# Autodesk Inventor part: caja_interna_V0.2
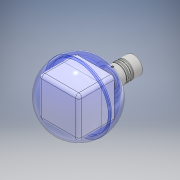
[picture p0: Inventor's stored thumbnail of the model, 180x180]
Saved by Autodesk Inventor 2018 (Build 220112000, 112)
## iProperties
Created: 2018-09
Part Number: caja_interna_V0.2
Material: Generic
Document SubType Name: Modeling
Designer: Gordillo
Density: 1 g/cm^3
Appearance: Default
Author: Gordillo
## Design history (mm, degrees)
sketch "Sketch1"
  geometry: L1 (125, 125)-(-125, 125); L2 (-125, 125)-(-125, -125); L3 (-125, -125)-(125, -125); L4 (125, -125)-(125, 125); L5 (-175, 0)-(175, 0) reference; L6 (0, -175)-(0, 175) reference; 1 further point
  constraints: 8 end point, 2 parallel, 1 horizontal, 1 perpendicular, 2 other
  dimensions: "d0" = 250 distance of L3.end L2.end; "d1" = 250 distance of L2.end L1.end
extrude "Extrusion1" new body sketch "Sketch1" distance "d2" = 220; taper "d3" = 0 deg
fillet "Fillet1" dims "d5" = 20
sketch "Sketch2"
  geometry: L1 (20, 125)-(220, 125) reference; L2 (120, 125)-(120, -125); L3 (220, -125)-(20, -125) reference; L4 (120, 125)-(120, 205); L5 (120, 0)-(-80, 0); L6 (-153.152, 0)-(282.192, 0) reference; A1 r 203.001 centre (122.991, 2.021) between (120, 205) and (-80, 0); 1 further point
  constraints: 6 end point, 3 midpoint, 2 point on circle, 1 centre point, 1 horizontal, 1 vertical
  dimensions: "d6" = 200 distance of L5.start L5.end; "d8" = 80 distance of L2.start L4.end
revolve "Revolution1" sketch "Sketch2" stored, may be unused: angle "d9" = 90 deg
combine "Combine1"
shell "Shell2" dims "d10" = 25
sketch "Sketch3"
  geometry: L1 (100, 100)-(100, -100) reference; L2 (100, -100)-(-100, -100) reference; L3 (-100, -100)-(-100, 100) reference; L4 (-100, 100)-(100, 100) reference; L5 (105, 125)-(-105, 125) reference; L6 (-125, 105)-(-125, -105) reference; L7 (-105, -125)-(105, -125) reference; L8 (125, -105)-(125, 105) reference; L9 (-105, 125)-(105, 125) reference; L10 (125, 105)-(125, -105) reference; L11 (105, -125)-(-105, -125) reference; L12 (-125, -105)-(-125, 105) reference; L13 (-105, 125)-(105, 125) reference; L14 (105, 125)-(-105, 125); L15 (-105, 125)-(-125, 105); L16 (-125, -105)-(-125, 105) reference; L17 (-125, -105)-(-105, -125); L18 (125, 105)-(125, -105) reference; L19 (105, -125)-(125, -105); L20 (125, -105)-(125, 105); L21 (-125, 105)-(-105, 105) reference; L22 (-125, 105)-(-125, -105); L23 (-105, -125)-(105, -125); C1 r 205 at (0, 0) reference; C2 r 189 at (0, 0); C3 r 205 at (0, 0) reference; A1 r 20 centre (105, 105) between (125, 105) and (105, 125) reference; A2 r 20 centre (-105, 105) between (-105, 125) and (-125, 105) reference; A3 r 20 centre (-105, -105) between (-125, -105) and (-105, -125) reference; A4 r 20 centre (105, -105) between (105, -125) and (125, -105) reference; A5 r 20 centre (-105, 105) between (-105, 125) and (-125, 105) reference; A6 r 20 centre (105, 105) between (125, 105) and (105, 125) reference; A7 r 20 centre (105, -105) between (105, -125) and (125, -105) reference; A8 r 20 centre (-105, -105) between (-125, -105) and (-105, -125) reference; A9 r 20 centre (105, 105) between (125, 105) and (105, 125) reference; A10 r 20 centre (105, 105) between (125, 105) and (105, 125); A11 r 20 centre (105, -105) between (105, -125) and (125, -105) reference; A12 r 20 centre (105, -105) between (105, -125) and (125, -105); A13 r 20 centre (-105, -105) between (-125, -105) and (-105, -125); A14 r 20 centre (-105, 105) between (-105, 125) and (-125, 105) reference; A15 r 20 centre (-105, 105) between (-105, 125) and (-125, 105); A16 r 20 centre (-105, -105) between (-125, -105) and (-105, -125); A17 r 20 centre (-105, -105) between (-125, -105) and (-105, -125); A18 r 20 centre (105, -105) between (105, -125) and (125, -105); A19 r 20 centre (-105, -105) between (-125, -105) and (-105, -125) reference; A20 r 20 centre (-105, -105) between (-125, -105) and (-105, -125); 1 further point
  constraints: 16 point on circle, 14 end point, 9 centre point, 3 perpendicular, 3 tangent, 2 collinear, 1 concentric, 1 vertical
  dimensions: "d11" = 16 radial gap between concentric circles of C1 C2
extrude "Extrusion2" join sketch "Sketch3" distance "d12" = 20; taper "d13" = 0 deg
sketch "Sketch4"
  geometry: L1 (189, 140)-(-189, 140) reference; L2 (205, 120)-(-205, 120) reference; L3 (189, 120)-(189, 140) reference; L4 (189, 140)-(-189, 140) reference; L5 (-189, 120)-(189, 120) reference; L6 (-125, 20)-(-125, 220) reference; L7 (-125, 220)-(-105, 220) reference; L8 (-205, 120)-(-189, 120); L9 (-189, 120)-(-189, 140); L10 (205, 120)-(-205, 120) reference; L11 (-189, 140)-(-125, 140); L12 (0, 120)-(0, 320); L13 (-125, 140)-(0, 140); L14 (0, -168.98)-(0, 453.807) reference; L15 (0, 304)-(-55, 304); L16 (-55, 304)-(-55, 315.014); L17 (0, 304)-(0, 298); L18 (0, 304)-(-55, 304); L19 (-55, 304)-(-55, 315.014); L20 (-87, 304.444)-(-67, 304.444); L21 (-67, 304.444)-(-67, 311.765); A1 r 195 centre (-10.071, 125.26) between (0, 320) and (-205, 120); A2 r 177.861 centre (-12.205, 120.558) between (0, 298) and (-189, 140); A3 r 195 centre (-10.071, 125.26) between (-55, 315.014) and (-205, 120); A4 r 177.861 centre (-12.205, 120.558) between (0, 298) and (-189, 140); 2 further points
  constraints: 24 end point, 11 point on circle, 5 point on line, 4 centre point, 4 perpendicular, 3 vertical, 2 collinear, 2 concentric, 2 midpoint, 1 horizontal
  dimensions: "d14" = 200 distance of L12.start L12.end; "d15" = 195 radius of A1; "d16" = 22 distance of L12.end L17.end; "d26" = 55 distance of L15.start L15.end; "d27" = 16 distance from line of L12.end L15; "d28" = 177.86112 radius of A2; "d30" = 12 distance between parallel lines of L16 L21; "d31" = 20 distance of L20.start L20.end
  node "Projected Loop3"
  node "Projected Loop4"
derived "tubo_electrovalvula_V0.1.ipt"
feature "Move Body1"
feature "Move Body3"
revolve "Revolution4" stored, may be unused: angle "d32" = 90 deg
node "cajacorchopan"
node "semicirculo_inferior"
node "Projected Loop1"
node "Projected Loop2"
feature "Solid1::tubo_electrovalvula_V0.1.ipt" dims "d18" = 10
tag "TaggingFeature1"
node "semicirculo_superior"
node "tubo inflado"
other parameters: "d19" = 270 deg, "d23" = 0
